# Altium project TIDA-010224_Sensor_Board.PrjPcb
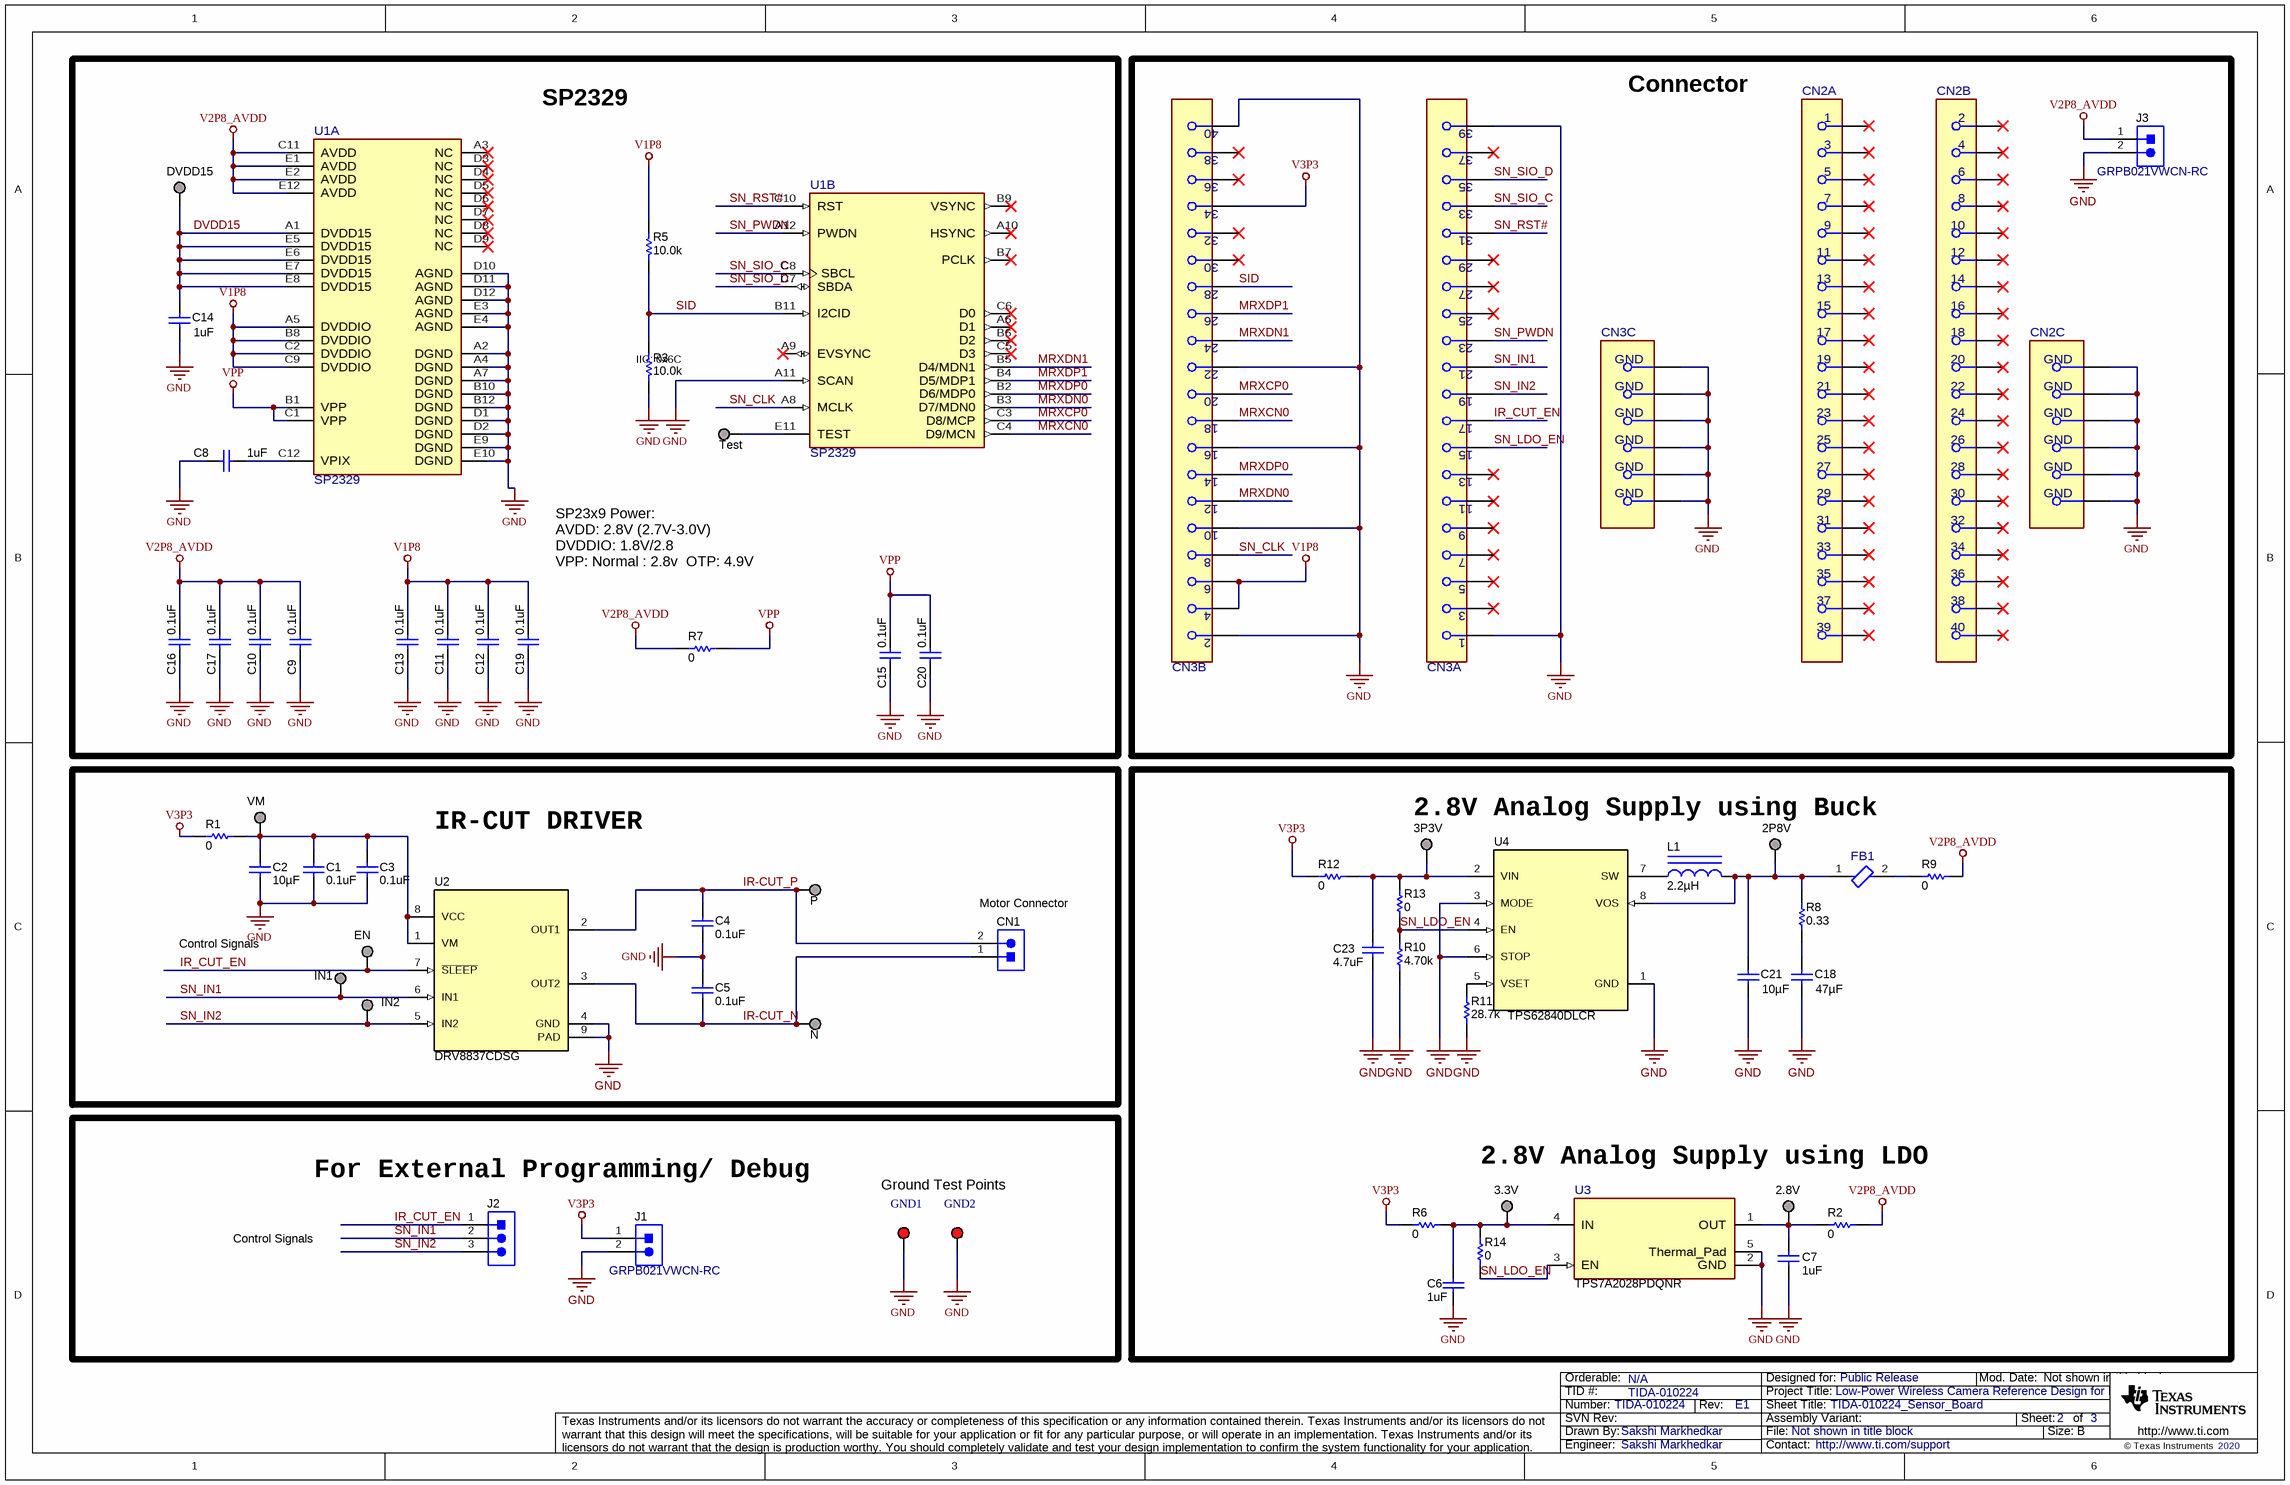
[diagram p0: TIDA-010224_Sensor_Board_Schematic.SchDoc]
TID: TIDA-010224; TechSupport: http://www.ti.com/support; SCH_Rev: E1; PRJ_Title: Low-Power Wireless Camera Reference Design for Extended Battery Life; PRJ_Number: TIDA-010224; PRJ_Engineer: Sakshi Markhedkar; PRJ_Customer: Public Release; PCB_Rev: E1; PCB_Layout: Tessolve; EVM_Orderable: N/A; CopyrightYear: 2020
3 sheets, 75 parts. Net scope: global (net labels, ports and power ports of the same name join across sheets).
Board file: TIDA-010224_Sensor_Board_PCB.PcbDoc
Sheets:
  TIDA-010224_Sensor_Board_Schematic.SchDoc
  TIDA-010224_Sensor_Board_Hardware.SchDoc
  TIDA-010224_CoverSheet.SchDoc

## Sheet TIDA-010224_Sensor_Board_Schematic.SchDoc: TIDA-010224_Sensor_Board
size 431 x 279 mm; Date: Not shown in title block; ApprovedBy: Not shown in title block; CheckedBy: Not shown in title block; Author: Not shown in title block; CompanyName: Not shown in title block; DrawnBy: Sakshi Markhedkar; Engineer: Not shown in title block; Organization: Not shown in title block; Address1: Not shown in title block; Address2: Not shown in title block; Address3: Not shown in title block; Address4: Not shown in title block; DocumentNumber: 2; Revision: Use project parameter SCH_Rev; SheetNumber: 2; SheetTotal: 3; PageSetup: Record=PageOptions¦CenterHorizontal=True¦CenterVertical=True¦PrintScale=1.00¦XCorrection=1.00¦YCorrection=1.00¦PrintKind=0¦BorderSize=5000000¦LeftOffset=0¦BottomOffset=0¦Orientation=2¦PaperLength=1000¦PaperWidth=1000¦Scale=100¦PaperSource=15¦PrintQuality=600¦MediaType=1¦DitherType=10¦PaperKind=Letter¦PrintScaleMode=1

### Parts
2.8V  2.8V  [TP_25MIL-SMT]  (value not drawn)  (no BOM)
2P8V  2.8V  [TP_25MIL-SMT]  (value not drawn)  (no BOM)
3.3V  3.3V  [TP_25MIL-SMT]  (value not drawn)  (no BOM)
3P3V  3.3V  [TP_25MIL-SMT]  (value not drawn)  (no BOM)
C1  ValueDisplayed: 0.1uF  [0402]  (hidden comment: GRM155R71C104KA88D)
C2  Cap_F: 10µF  [0603]  (hidden comment: GRM188Z71A106MA73D)
C3  ValueDisplayed: 0.1uF  [0402]  (hidden comment: GRM155R71C104KA88D)
C4  ValueDisplayed: 0.1uF  [0402]  (hidden comment: GRM155R71C104KA88D)
C5  ValueDisplayed: 0.1uF  [0402]  (hidden comment: GRM155R71C104KA88D)
C6  ValueDisplayed: 1uF  [0402]  (hidden comment: C1005X7S1A105K050BC)
C7  ValueDisplayed: 1uF  [0402]  (hidden comment: C1005X7S1A105K050BC)
C8  ValueDisplayed: 1uF  [0402]  (hidden comment: C1005X7S1A105K050BC)
C9  ValueDisplayed: 0.1uF  [0402S]  (hidden comment: GRM155R71C104KA88D)
C10  ValueDisplayed: 0.1uF  [0402S]  (hidden comment: GRM155R71C104KA88D)
C11  ValueDisplayed: 0.1uF  [0402S]  (hidden comment: GRM155R71C104KA88D)
C12  ValueDisplayed: 0.1uF  [0402S]  (hidden comment: GRM155R71C104KA88D)
C13  ValueDisplayed: 0.1uF  [0402S]  (hidden comment: GRM155R71C104KA88D)
C14  ValueDisplayed: 1uF  [0402]  (hidden comment: C1005X7S1A105K050BC)
C15  ValueDisplayed: 0.1uF  [0402S]  (hidden comment: GRM155R71C104KA88D)
C16  ValueDisplayed: 0.1uF  [0402S]  (hidden comment: GRM155R71C104KA88D)
C17  ValueDisplayed: 0.1uF  [0402S]  (hidden comment: GRM155R71C104KA88D)
C18  Cap_F: 47µF  [0805_HV]  (hidden comment: GRM21BR61A476ME15L)
C19  ValueDisplayed: 0.1uF  [0402S]  (hidden comment: GRM155R71C104KA88D)
C20  ValueDisplayed: 0.1uF  [0402S]  (hidden comment: GRM155R71C104KA88D)
C21  ValueDisplayed: 10µF  [0402_070]  (hidden comment: C0402C106M9PACTU)
C23  ValueDisplayed: 4.7uF  [0402]  (hidden comment: GRM155R61A475MEAAD)
CN1  53398-0271  [0533980271]  (value not drawn)
CN2  FX12B-40S-0.4SV(30)  [FP-FX12B-40S-0.4SV(30)_RCPT40-MFG]  (value not drawn)  (parts A,B,C of 3)
CN3  FX12B-40S-0.4SV(30)  [FP-FX12B-40S-0.4SV(30)_RCPT40-MFG]  (value not drawn)  (parts A,B,C of 3)
DVDD15  DVDD  [TP_25MIL-SMT]  (value not drawn)  (no BOM)
EN  EN  [TP_25MIL-SMT]  (value not drawn)  (no BOM)
FB1  BLM18KG121TN1D  [FP-BLM18KG121TN1D_0603-MFG]  (value not drawn)
GND1  GND  [Keystone5005]  (value not drawn)
GND2  GND  [Keystone5005]  (value not drawn)
IN1  IN1  [TP_25MIL-SMT]  (value not drawn)  (no BOM)
IN2  IN2  [TP_25MIL-SMT]  (value not drawn)  (no BOM)
J1  GRPB021VWCN-RC  [Sullins_xxxB021VWCN]
J2  M20-8770342  [Harwin_M20-87703]  (value not drawn)
J3  GRPB021VWCN-RC  [Sullins_xxxB021VWCN]
L1  ValueDisplayed: 2.2µH  [DFE201612E]  (hidden comment: DFE201612E-2R2M=P2)
N  N  [TP_25MIL-SMT]  (value not drawn)  (no BOM)
P  P  [TP_25MIL-SMT]  (value not drawn)  (no BOM)
R1  ValueDisplayed: 0  [0402]  (hidden comment: Resistor)
R2  ValueDisplayed: 0  [0402]  (hidden comment: Resistor)
R3  ValueDisplayed: 10.0k  [0402S]  (hidden comment: RC0402FR-0710KL)
R5  ValueDisplayed: 10.0k  [0402S]  (hidden comment: RC0402FR-0710KL)
R6  ValueDisplayed: 0  [0402]  (hidden comment: Resistor)
R7  ValueDisplayed: 0  [0402S]  (hidden comment: Resistor)
R8  ValueDisplayed: 0.33  [0402]  (hidden comment: ERJ-2BQFR33X)
R9  ValueDisplayed: 0  [0402]  (hidden comment: Resistor)
R10  ValueDisplayed: 4.70k  [0402]  (hidden comment: ERJ-2RKF4701X)
R11  ValueDisplayed: 28.7k  [0402]  (hidden comment: CRCW040228K7FKED)
R12  ValueDisplayed: 0  [0402]  (hidden comment: Resistor)
R13  ValueDisplayed: 0  [0402]  (hidden comment: Resistor)
R14  ValueDisplayed: 0  [0402]  (hidden comment: Resistor)
Test  Test  [TP_25MIL-SMT]  (value not drawn)  (no BOM)
U1  SP2329  [FP-SP2329_CSP60-IPC_C]  (parts A,B of 2)
U2  DRV8837CDSG  [DSG0008A]
U3  TPS7A2028PDQNR  [DQN0004A-MFG]
U4  TPS62840DLCR  [DLC0008B]
VM  VM  [TP_25MIL-SMT]  (value not drawn)  (no BOM)

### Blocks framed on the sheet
SP2329: C8-C17 C19 C20 DVDD15 R3 R5 R7 Test U1
Connector: CN2 CN3 J3
IR-CUT DRIVER: C1-C5 CN1 EN IN1 IN2 N P R1 U2 VM
For External Programming/ Debug: GND1 GND2 J1 J2

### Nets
GND: C1.1 C2.2 C3.1 C4.1 C5.2 C6.2 C7.2 C8.2 C9.1 C10.1 C11.1 C12.1 C13.1 C14.2 C15.1 C16.1 C17.1 C18.2 C19.1 C20.1 C21.2 C23.2 CN2.41(GND) CN2.42(GND) CN2.43(GND) CN2.44(GND) CN2.45(GND) CN2.46(GND) CN3.1 CN3.2 CN3.10 CN3.16 CN3.22 CN3.39 CN3.40 CN3.41(GND) CN3.42(GND) CN3.43(GND) CN3.44(GND) CN3.45(GND) CN3.46(GND) GND1.1 GND2.1 J1.2 J3.2 R3.1 R10.1 R11.1 U1.A2(DGND) U1.A4(DGND) U1.A7(DGND) U1.A11(SCAN) U1.B10(DGND) U1.B12(DGND) U1.D1(DGND) U1.D2(DGND) U1.D10(AGND) U1.D11(AGND) U1.D12(AGND) U1.E3(AGND) U1.E4(AGND) U1.E9(DGND) U1.E10(DGND) U2.4(GND) U2.9(PAD) U3.2(GND) U3.5(Thermal_Pad) U4.1(GND) U4.3(MODE) U4.6(STOP)
V1P8: C11.2 C12.2 C13.2 C19.2 CN3.4 CN3.6 R5.2 U1.A5(DVDDIO) U1.B8(DVDDIO) U1.C2(DVDDIO) U1.C9(DVDDIO)
V2P8_AVDD: C9.2 C10.2 C16.2 C17.2 J3.1 R2.1 R7.2 R9.1 U1.C11(AVDD) U1.E1(AVDD) U1.E2(AVDD) U1.E12(AVDD)
V3P3: CN3.34 J1.1 R1.2 R6.2 R12.2
VPP: C15.2 C20.2 R7.1 U1.B1(VPP) U1.C1(VPP)
DVDD15: C14.1 DVDD15.1 U1.A1(DVDD15) U1.E5(DVDD15) U1.E6(DVDD15) U1.E7(DVDD15) U1.E8(DVDD15)
IR-CUT_N: C5.1 CN1.1 N.1 U2.3(OUT2)
IR-CUT_P: C4.2 CN1.2 P.1 U2.2(OUT1)
IR_CUT_EN: CN3.17 EN.1 J2.1 U2.7(~{SLEEP})
MRXCN0: CN3.18 U1.C4(D9/MCN)
MRXCP0: CN3.20 U1.C3(D8/MCP)
MRXDN0: CN3.12 U1.B3(D7/MDN0)
MRXDN1: CN3.24 U1.B5(D4/MDN1)
MRXDP0: CN3.14 U1.B2(D6/MDP0)
MRXDP1: CN3.26 U1.B4(D5/MDP1)
SID: CN3.28 R3.2 R5.1 U1.B11(I2CID)
SN_CLK: CN3.8 U1.A8(MCLK)
SN_IN1: CN3.21 IN1.1 J2.2 U2.6(IN1)
SN_IN2: CN3.19 IN2.1 J2.3 U2.5(IN2)
SN_LDO_EN: CN3.15 R10.2 R13.2 R14.2 U3.3(EN) U4.4(EN)
SN_PWDN: CN3.23 U1.A12(PWDN)
SN_RST#: CN3.31 U1.C10(RST)
SN_SIO_C: CN3.33 U1.C8(SBCL)
SN_SIO_D: CN3.35 U1.C7(SBDA)
Net2.8V_1: 2.8V.1 C7.1 R2.2 U3.1(OUT)
Net2P8V_1: 2P8V.1 C21.1 FB1.1 L1.2 R8.2 U4.8(VOS)
Net3.3V_1: 3.3V.1 C6.1 R6.1 R14.1 U3.4(IN)
Net3P3V_1: 3P3V.1 C23.1 R12.1 R13.1 U4.2(VIN)
NetC1_2: C1.2 C2.1 C3.2 R1.1 U2.1(VM) U2.8(VCC) VM.1
NetC8_1: C8.1 U1.C12(VPIX)
NetC18_1: C18.1 R8.1
NetFB1_2: FB1.2 R9.2
NetL1_1: L1.1 U4.7(SW)
NetR11_2: R11.2 U4.5(VSET)
NetTest_1: Test.1 U1.E11(TEST)

Not connected (* = marked no-connect by the designer): CN2 1* 2* 3* 4* 5* 6* 7* 8* 9* 10* 11* 12* 13* 14* 15* 16* 17* 18* 19* 20* 21* 22* 23* 24* 25* 26* 27* 28* 29* 30* 31* 32* 33* 34* 35* 36* 37* 38* 39* 40*; CN3 3* 5* 7* 9* 11* 13* 25* 27* 29* 30* 32* 36* 37* 38*; U1 A3(NC)* A6(D1)* A9(EVSYNC)* A10(HSYNC)* B6(D2)* B7(PCLK)* B9(VSYNC)* C5(D3)* C6(D0)* D3(NC)* D4(NC)* D5(NC)* D6(NC)* D7(NC)* D8(NC)* D9(NC)*

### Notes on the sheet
- (near R3) IIC: 0x6C
- SP23x9 Power:
  AVDD: 2.8V (2.7V-3.0V)
  DVDDIO: 1.8V/2.8
  VPP: Normal : 2.8v  OTP: 4.9V
- 2.8V Analog Supply using Buck
- (near CN1) Motor Connector
- Control Signals
- 2.8V Analog Supply using LDO
- Ground Test Points

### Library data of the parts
2.8V 2P8V 3.3V 3P3V DVDD15 EN IN1 IN2 N P Test VM = CMP-0078143-2: TEST POINT.  No entry in BOM.
C1 C3-C5 = CMP-0006641-2: CAP, CERM, 0.1 uF, 16 V, +/- 10%, X7R, 0402; Manufacturer: MuRata; TaMin_C: -55°C; Polarized: N; SizeAreaWB_mm2: 3; Value1: Unknown; U/M: EA; Value: 0.1uF; TaMax_C: 125°C; SizeZ_mm: 0.6; SizeX_mm: 1; SizeY_mm: 0.5; Value2: 16V; Cap_F: 100nF; AEC Category: Q200
C2 = CMP-0007497-5: CAP, CERM, 10 uF, 10 V, +/- 20%, X7R, 0603; Manufacturer: MuRata; TaMin_C: -55°C; Polarized: N; SizeAreaWB_mm2: 4.68; Value1: Unknown; U/M: EA; Value: 10uF; TaMax_C: 125°C; SizeZ_mm: 1; SizeX_mm: 1.6; SizeY_mm: 0.8; Value2: 10V; SizeArea_mm2: 1.28; AEC Category: Q200
C6-C8 C14 = CMP-0006300-2: CAP, CERM, 1 uF, 10 V, +/- 10%, X7S, 0402; Manufacturer: TDK; TaMin_C: -55°C; ESR_ohm: 0.011416; Polarized: N; SizeAreaWB_mm2: 3; Value1: 0.011416 ohm; U/M: EA; Value: 1uF; TaMax_C: 125°C; SizeZ_mm: 0.6; SizeX_mm: 1; SizeY_mm: 0.5; Value2: 10V; Cap_F: 1µF; IRMS_A: 1.483A; AEC Category: Q200
C9-C13 C15-C17 C19 C20 = CMP-0006641-2: CAP, CERM, 0.1 uF, 16 V, +/- 10%, X7R, 0402; Manufacturer: MuRata; TaMin_C: -55°C; Polarized: N; SizeAreaWB_mm2: 3; Value1: Unknown; U/M: EA; Value: 0.1uF; TaMax_C: 125°C; SizeZ_mm: 0.6; SizeX_mm: 1; SizeY_mm: 0.5; Cap_Case: 0402; Value2: 16V; Cap_F: 100nF; AEC Category: Q200
C18 = CMP-0078699-1: CAP, CERM, 47 µF, 10 V,+/- 20%, X5R, 0805; Manufacturer: MuRata; TaMin_C: -55°C; Polarized: N; Green_Lifecycle: Active; SizeAreaWB_mm2: 6.75; Green_REACh: Passed; U/M: EA; Value: 47uF; TaMax_C: 85°C; SizeZ_mm: 1.45; SizeX_mm: 2; SizeY_mm: 1.25; Cap_Case: 0805; Value2: 10V; SizeArea_mm2: 2.5; AEC Category: Q200
C21 = CMP-0081134-1: CAP, CERM, 10 µF, 6.3 V,+/- 20%, X5R, 0402; Manufacturer: Kemet; TaMin_C: -55°C; ESR_ohm: 1m; Polarized: N; SizeAreaWB_mm2: 3; Value1: 0.001 ohm; U/M: EA; Value: 10uF; TaMax_C: 85°C; SizeZ_mm: 0.7; SizeX_mm: 1; SizeY_mm: 0.5; Cap_Case: 0402; Value2: 6.3V; AEC Category: Q200
C23 = CMP-0006582-2: CAP, CERM, 4.7 uF, 10 V, +/- 20%, X5R, 0402; Manufacturer: MuRata; TaMin_C: -55°C; Polarized: N; SizeAreaWB_mm2: 3; Value1: Unknown; U/M: EA; Value: 4.7uF; TaMax_C: 85°C; SizeZ_mm: 0.6; SizeX_mm: 1; SizeY_mm: 0.5; Value2: 10V; Cap_F: 4.7µF; AEC Category: Q200
CN1 = CMP-0055117-1: Plug, SMT, Vertical, 1.25mm, 1x2; Manufacturer: Molex; CT: FALSE; CompType: Header
CN2 CN3 = CMP-0089231-1: 40 Position Connector Receptacle, Outer Shroud Contacts Surface Mount; Manufacturer: Hirose; ContactFinish: Gold,Nickel; Current_A: 3dA; Voltage_V: 30V; AEC Qualified: No; Row_Count: 2; Conn Orientation: Vertical; Is Female: yes; Shrouded: true; Conn Gender: Female; DUT-Pitch_mm: 0.4mm; SizeZ_mm: 1.5mm
FB1 = CMP-0089995-1: 120 Ohms @ 100MHz 1 Power Line Ferrite Bead 0603 (1608 Metric) 3A 30mOhm; Manufacturer: Murata; DCR_ohm: 0.03; Impedance At Frequency: 120Ω @ 100MHz; Tolerance_%: 25%; AEC Qualified: No; SizeZ_mm: 0.75mm
GND1 GND2 = CMP-0055142-1: Test Point, Compact, Red, TH; Manufacturer: Keystone; CNHeader: FALSE; Green_Lifecycle: Active; Green_REACh: Passed; ContactFinish: Silver; CT: TRUE
J1 J3 = CMP-0054582-1: Header, 1.27 mm, 2x1, Gold, R/A, TH; Manufacturer: Sullins Connector Solutions; CNHeader: TRUE; Shrouded: N; Gender: Male; Row_Count: 1; Pitch_mm: 1.27; CT: FALSE
J2 = CMP-0075319-1: Header, 2.54mm, 3x1, Gold, SMT; Manufacturer: Harwin; CNHeader: True; Current_A: 3A; Green_Lifecycle: Active; Shrouded: N; Gender: Male; Green_REACh: Passed; Row_Count: 1; Pitch_mm: 2.54; CT: False; Cert_UL: Y
L1 = CMP-0080775-1: Inductor, Shielded, Metal Composite, 2.2 µH, 1.8 A, 0.116 ohm, SMD; Manufacturer: MuRata; Value: 2.2uH; AEC Category: Q200; AEC Qualified: N; DCR_ohm: 0.116; Imax_A: 1.8A; Irms: 1.8A @ 40C rise; Isat: 2.4A @ 30% inductance drop; SizeArea_mm2: 3.2; SizeAreaWB_mm2: 7.8; SizeX_mm: 2; SizeY_mm: 1.6; SizeZ_mm: 1.2
R1 R2 R6 R7 R9 R12-R14 = CMP-0026822-3: RES, 0, 5%, 0.063 W, AEC-Q200 Grade 0, 0402; PartNumber: CRCW04020000Z0ED; Manufacturer: Vishay-Dale; Value: 0; Value_Code: 0000; Power_W: 63mW; Value2: 0.063W; VDC_V: 50V; TempCo: 200 ppm/C; SizeArea_mm2: 0.5; SizeX_mm: 1; SizeZ_mm: 0.6; EIA_Code: E24; AEC Category: Q200; AEC Qualified: Y
R3 R5 = CMP-0078669-1: RES, 10.0 k, 1%, 0.063 W, 0402; Manufacturer: Yageo America; Power_W: 63mW; Green_Lifecycle: Active; TempCo: 100 ppm/C; Value_Code: 10k0; Green_REACh: Passed; Value: 10.0k; EIA_Code: E96; Res_ohm: 10k; SizeX_mm: 1; SizeY_mm: 0.5; SizeZ_mm: 0.6; Value2: 0.063W; AEC Qualified: N; AEC Category: Q200
R8 = CMP-0026635-2: RES, 0.33, 1%, 0.125 W, AEC-Q200 Grade 0, 0402; Manufacturer: Panasonic; Power_W: 125mW; TempCo: 250 ppm/C; Value_Code: R330; Value: 0.33; EIA_Code: E96; SizeX_mm: 1; SizeY_mm: 0.5; SizeZ_mm: 0.6; Value2: 0.125W; AEC Qualified: Y; AEC Category: Q200; AEC Grade: 0; SizeAreaWB_mm2: 3
R10 = CMP-0026700-1: RES, 4.70 k, 1%, 0.1 W, 0402; Manufacturer: Panasonic; Power_W: 100mW; TempCo: 100 ppm/C; Value_Code: 4k70; U/M: EA; Value: 4.70k; Res_ohm: 4.7k; SizeX_mm: 1; SizeY_mm: 0.5; SizeZ_mm: 0.6; Value2: 0.1W; VDC_V: 50V; AEC Category: Q200
R11 = CMP-0026220-2: RES, 28.7 k, 1%, 0.063 W, AEC-Q200 Grade 0, 0402; Manufacturer: Vishay-Dale; Power_W: 63mW; TempCo: 100 ppm/C; Value_Code: 28k7; Value: 28.7k; EIA_Code: E96; SizeX_mm: 1; SizeY_mm: 0.5; SizeZ_mm: 0.6; Value2: 0.063W; AEC Qualified: Y; VDC_V: 50V; AEC Category: Q200; AEC Grade: 0
U1 = CMP-0088584-2: 1/2.7-Inch 2-Mega Pixel CMOS Image Sensor; Manufacturer: SuperPix; SizeZ_mm: 0.808mm; AEC Qualified: No; Max Supply Voltage: 3V; Standoff Height: 0.1mm; Min Supply Voltage: 1.7V; Sensor Output: Other
U2 = CMP-0013449-3: 1-A Low-Voltage H-Bridge Driver, DSG0008A (WSON-8); Manufacturer: Texas Instruments; SizeZ_mm: 0.8; SizeX_mm: 2; SizeArea_mm2: 4; CompType: IC; U/M: EA; SizeAreaWB_mm2: 9
U3 = CMP-0090215-1: 300-mA, Ultra-Low-Noise, Low-IQ, High PSRR LDO; Manufacturer: Texas Instruments; Accuracy Percentage: 1.5%; Output Voltage: 0.8-5.5V; AEC Qualified: No; Min Supply Voltage: 1.6V; Output Type: AdjustableProgrammable; Standoff Height: 0mm; TJmax_C: +125°C; Max Supply Voltage: 6V; Number Of Outputs: 1; SizeZ_mm: 0.4mm; Dropout Voltage: 690mV; Nominal Supply Current: 6.5uA
U4 = CMP-0081431-4: Ultra low IQ Step Down Converter, DLC0008A (VSON-HR-8); Alternate Manufacturer: Texas Instruments; SizeY_mm: 2; SizeZ_mm: 1; SizeArea_mm2: 3; AEC Qualified: N; AEC Category: Q200; SizeAreaWB_mm2: 7.5; CompType: IC; SizeX_mm: 1.5

## Sheet TIDA-010224_Sensor_Board_Hardware.SchDoc: TIDA-010224_Sensor_Board_Hardware
size 431 x 279 mm; Date: Not shown in title block; ApprovedBy: Not shown in title block; CheckedBy: Not shown in title block; Author: Not shown in title block; CompanyName: Not shown in title block; DrawnBy: Sakshi Markhedkar; Engineer: Not shown in title block; Organization: Not shown in title block; Address1: Not shown in title block; Address2: Not shown in title block; Address3: Not shown in title block; Address4: Not shown in title block; DocumentNumber: 3; Revision: Use project parameter SCH_Rev; SheetNumber: 3; SheetTotal: 3; PageSetup: Record=PageOptions¦CenterHorizontal=True¦CenterVertical=True¦PrintScale=1.00¦XCorrection=1.00¦YCorrection=1.00¦PrintKind=0¦BorderSize=5000000¦LeftOffset=0¦BottomOffset=0¦Orientation=2¦PaperLength=1000¦PaperWidth=1000¦Scale=100¦PaperSource=15¦PrintQuality=600¦MediaType=1¦DitherType=10¦PaperKind=Letter¦PrintScaleMode=1
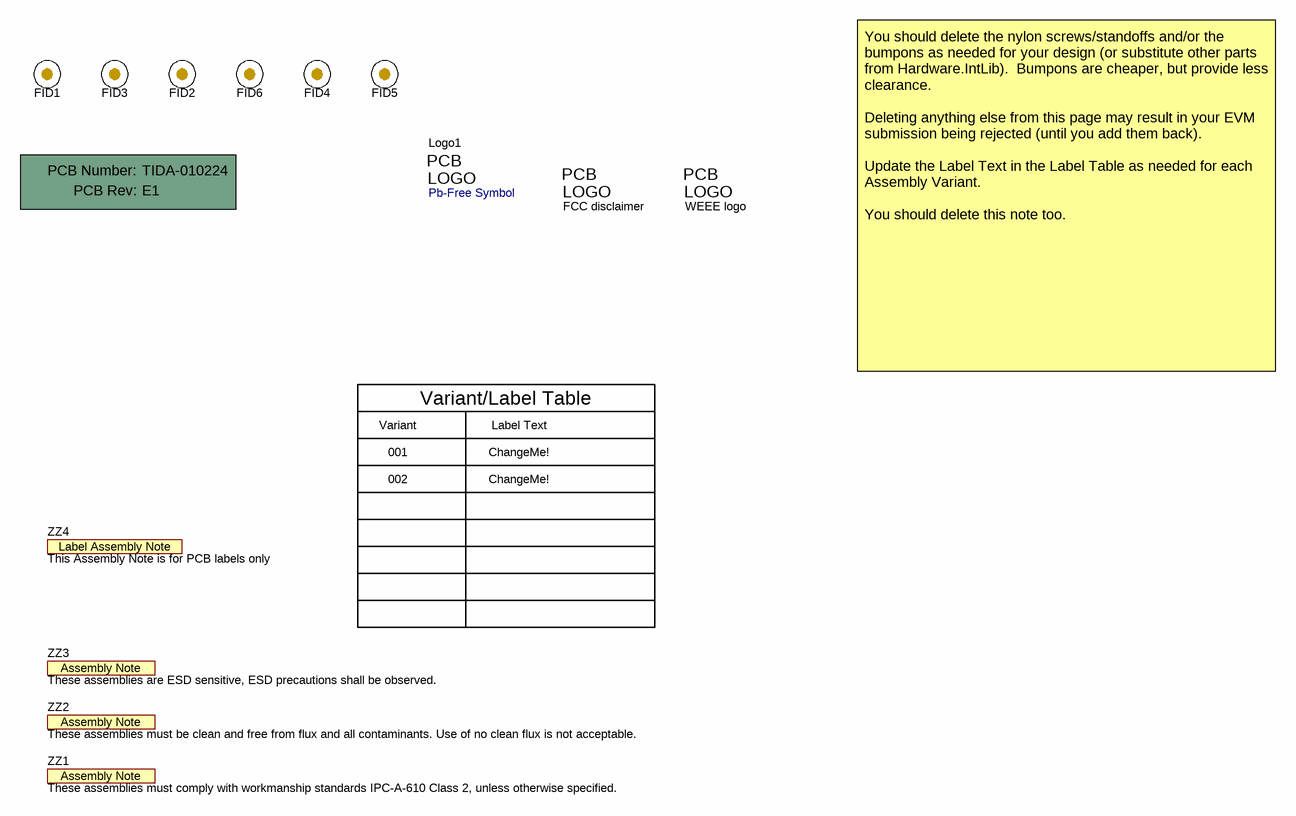
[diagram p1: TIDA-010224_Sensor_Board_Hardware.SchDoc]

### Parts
!PCB  Printed Circuit Board  (value not drawn)  (mechanical)
FID1  Fiducial  [Fiducial10-20]  (value not drawn)
FID2  Fiducial  [Fiducial10-20]  (value not drawn)
FID3  Fiducial  [Fiducial10-20]  (value not drawn)
FID4  Fiducial  [Fiducial10-20]  (value not drawn)
FID5  Fiducial  [Fiducial10-20]  (value not drawn)
FID6  Fiducial  [Fiducial10-20]  (value not drawn)
Logo1  Pb-Free Symbol  [Pb-Free_Overlay_Small]  (no BOM)
Logo2  WEEE logo  [WEEE_Minimum]  (no BOM)
Logo3  FCC disclaimer  [FCC_disclaimer_stacked]  (no BOM)
ZZ1  These assemblies must comply with workmanship standards IPC-A-610 Class 2, unless otherwise specified.  [AssemblyNote]  (no BOM)
ZZ2  These assemblies must be clean and free from flux and all contaminants. Use of no clean flux is not acceptable.  [AssemblyNote]  (no BOM)
ZZ3  These assemblies are ESD sensitive, ESD precautions shall be observed.  [AssemblyNote]  (no BOM)
ZZ4  This Assembly Note is for PCB labels only  [AssemblyNoteLabel]  (no BOM)

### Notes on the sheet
- Variant
- Variant/Label Table
- Label Text
- You should delete the nylon screws/standoffs and/or the bumpons as needed for your design (or substitute other parts from Hardware.IntLib).  Bumpons are cheaper, but provide less clearance.
  Deleting anything else from this page may result in your EVM submission being rejected (until you add them back).
  Update the Label Text in the Label Table as needed for each Assembly Variant.
  You should delete this note too.
- 001
- 002
- ChangeMe!

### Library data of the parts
!PCB = CMP-0003618-2: Manufacturer: Any; PartNumber: TIDA-010224
FID1-FID6 = CMP-0077181-1: Fiducial mark.  There is nothing to buy or mount.
Logo1 = CMP-0074839-1: SymbolCreator: a0412235
Logo2 = CMP-0074769-1
Logo3 = CMP-0074847-1: FCC_disclaimer; Library Reference: Logo
ZZ1 = CMP-0077238-1
ZZ2 = CMP-0077237-1
ZZ3 = CMP-0077236-1
ZZ4 = CMP-0003616-3

## Sheet TIDA-010224_CoverSheet.SchDoc: TIDA-010224_CoverSheet
size A2; Date: Not shown in title block; ApprovedBy: Not shown in title block; CheckedBy: Not shown in title block; Author: Not shown in title block; CompanyName: Not shown in title block; DrawnBy: Sakshi Markhedkar; Engineer: Not shown in title block; Organization: Not shown in title block; Address1: Not shown in title block; Address2: Not shown in title block; Address3: Not shown in title block; Address4: Not shown in title block; DocumentNumber: 1; Revision: Use project parameter SCH_Rev; SheetNumber: 1; SheetTotal: 3; PageSetup: Record=PageOptions¦CenterHorizontal=True¦CenterVertical=True¦PrintScale=1.00¦XCorrection=1.00¦YCorrection=1.00¦PrintKind=0¦BorderSize=5000000¦LeftOffset=0¦BottomOffset=0¦Orientation=2¦PaperLength=1000¦PaperWidth=1000¦Scale=100¦PaperSource=15¦PrintQuality=600¦MediaType=1¦DitherType=10¦PaperKind=Letter¦PrintScaleMode=1

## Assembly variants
001: not fitted C6 C7 C18 FID1 FID2 FID3 GND1 GND2 R2 R5 R6 R8 R14 U3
